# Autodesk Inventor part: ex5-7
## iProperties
Created: 2006-03
Part Number: ex5-7
Document SubType Name: Modeling
Designer: Elise Moss
Author: Elise Moss
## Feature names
1. Extrusion1
2. Hole1
3. Shell1
